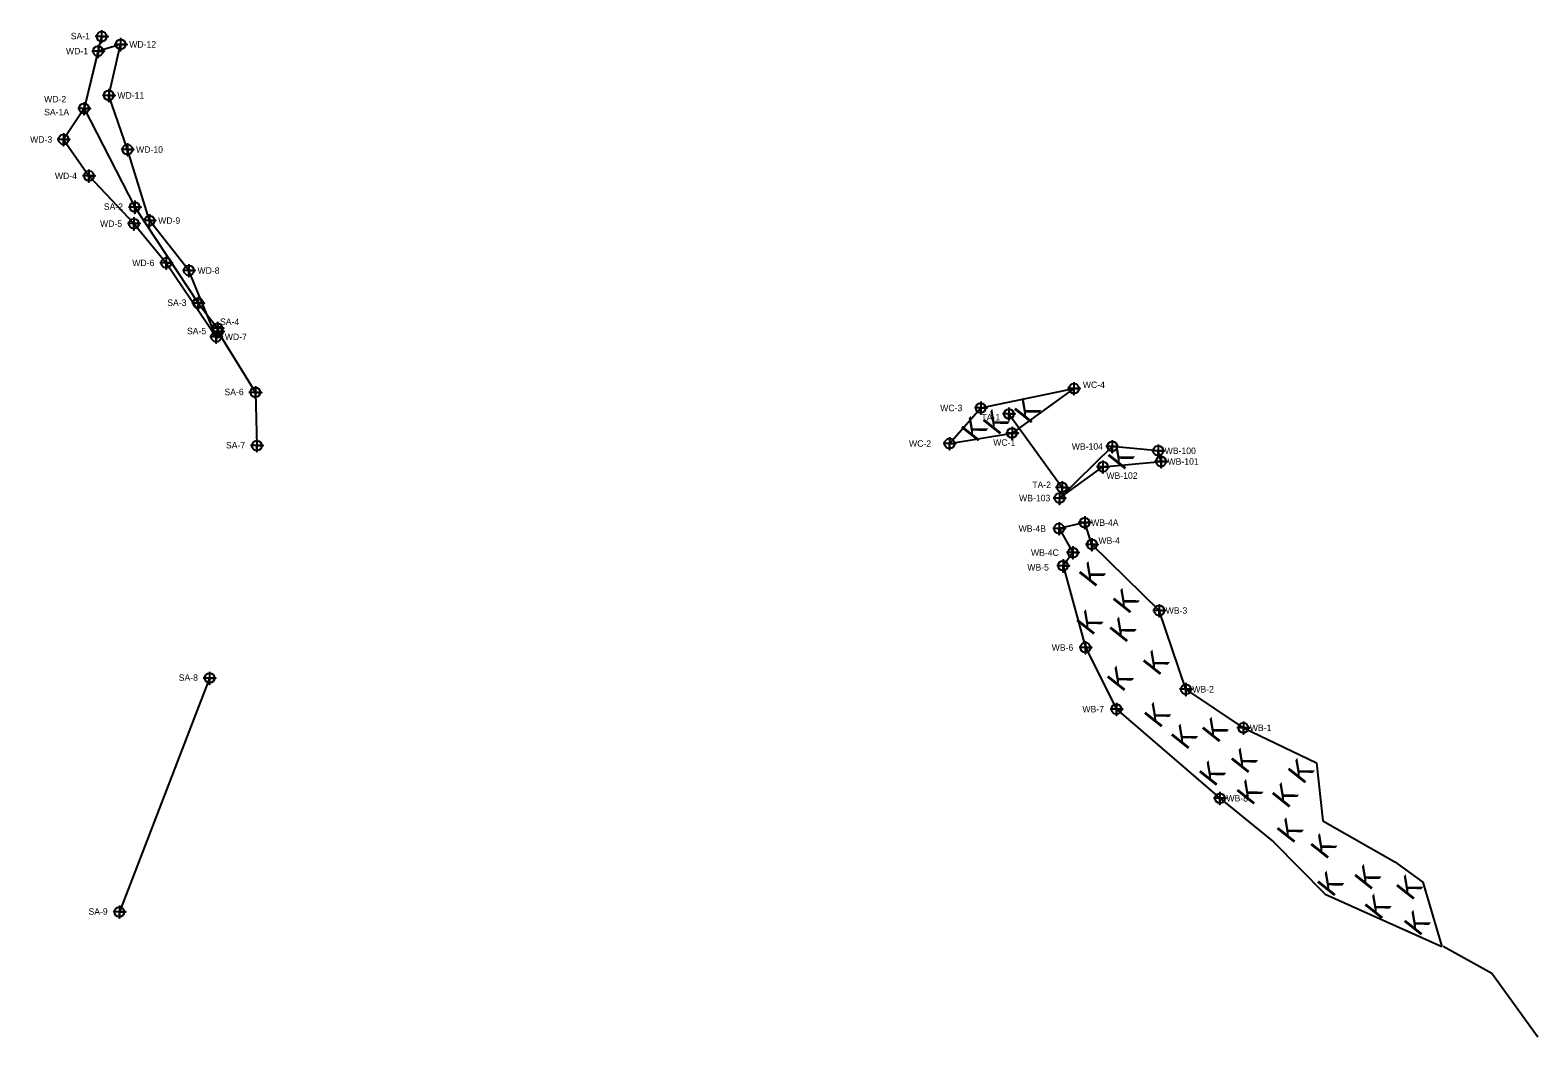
# Model space of a CAD drawing. Extents: x 1487542 to 1488992, y 498221 to 499418.
# Drawn here: x 1487542 to 1488253, y 498234 to 498709 of the extents above; entities that cross this region are included whole.
import ezdxf

# ---------------------------------------------------------------- set-up
doc = ezdxf.new("R2010")
doc.units = 0
for name, color, linetype in [('Exist Environmental Wetland Boundary', 7, 'Continuous'), ('Exist Environmental Wetland Boundary Cogo Point CELL', 7, 'Continuous'), ('Exist Environmental Wetland Boundary Text', 7, 'Continuous'), ('Exist Hydro Jurisdictional Stream or Body of Water Mitigable', 7, 'Continuous'), ('Exist Hydro Jurisdictional Stream or Body of Water Mitigable Cogo Point CELL', 7, 'Continuous'), ('Exist Hydro Jurisdictional Stream or Body of Water Mitigable Text', 7, 'Continuous'), ('WEX', 7, 'Continuous')]:
    doc.layers.add(name, color=color, linetype=linetype)

msp = doc.modelspace()

# ---------------------------------------------------------------- linework, layer by layer
at = {"layer": 'Exist Environmental Wetland Boundary'}
for p, q in [((1487989.85, 498530.79), (1488033.83, 498539.94)), ((1488033.83, 498539.94), (1488004.63, 498518.96)), ((1487975.14, 498514.02), (1487989.85, 498530.79)), ((1487975.14, 498514.02), (1488004.63, 498518.96)), ((1488027.05, 498488.31), (1488051.91, 498512.67)), ((1488073.57, 498510.61), (1488051.91, 498512.67)), ((1488047.52, 498503.04), (1488074.9, 498505.57)), ((1488074.9, 498505.57), (1488073.57, 498510.61)), ((1488027.05, 498488.31), (1488047.52, 498503.04)), ((1488027.05, 498488.31), (1488027.05, 498488.31)), ((1488038.89, 498476.72), (1488026.84, 498473.92)), ((1488042.31, 498466.47), (1488038.89, 498476.72)), ((1488026.84, 498473.92), (1488033.35, 498462.59)), ((1488033.35, 498462.59), (1488028.68, 498456.43)), ((1488042.31, 498466.47), (1488074.05, 498435.29)), ((1488028.68, 498456.43), (1488039.22, 498417.82)), ((1488086.63, 498398.13), (1488074.05, 498435.29)), ((1488039.22, 498417.82), (1488053.85, 498388.8)), ((1488113.73, 498379.96), (1488086.63, 498398.13)), ((1488053.85, 498388.8), (1488102.69, 498346.76)), ((1488113.73, 498379.96), (1488148.21, 498363.39)), ((1488148.21, 498363.39), (1488151.15, 498336.13)), ((1488102.69, 498346.76), (1488127.91, 498326.29)), ((1488151.15, 498336.13), (1488185.16, 498316.76)), ((1488127.91, 498326.29), (1488152.35, 498301.47)), ((1488185.16, 498316.76), (1488198.43, 498307.27)), ((1488198.43, 498307.27), (1488207.36, 498276.87)), ((1488152.35, 498301.47), (1488207.36, 498276.87))]:
    msp.add_line(p, q, dxfattribs=at)
msp.add_lwpolyline([(1487629.27, 498564.35), (1487616.38, 498595.61), (1487597.86, 498619.14), (1487587.44, 498652.62), (1487578.6, 498678.18), (1487584.22, 498702.23), (1487573.56, 498699.03), (1487566.96, 498672), (1487557.29, 498657.39), (1487569.27, 498640.21), (1487590.45, 498617.69), (1487605.69, 498599.19)], close=True, dxfattribs=at)
at = {"layer": 'Exist Environmental Wetland Boundary Cogo Point CELL'}
for points in [[(1487584.22, 498705.23), (1487584.22, 498699.23), (1487584.22, 498702.23), (1487587.22, 498702.23), (1487581.22, 498702.23)], [(1487573.56, 498702.03), (1487573.56, 498696.03), (1487573.56, 498699.03), (1487576.56, 498699.03), (1487570.56, 498699.03)], [(1487566.96, 498675), (1487566.96, 498669), (1487566.96, 498672), (1487569.96, 498672), (1487563.96, 498672)], [(1487578.6, 498681.18), (1487578.6, 498675.18), (1487578.6, 498678.18), (1487581.6, 498678.18), (1487575.6, 498678.18)], [(1487557.29, 498660.39), (1487557.29, 498654.39), (1487557.29, 498657.39), (1487560.29, 498657.39), (1487554.29, 498657.39)], [(1487587.44, 498655.62), (1487587.44, 498649.62), (1487587.44, 498652.62), (1487590.44, 498652.62), (1487584.44, 498652.62)], [(1487569.27, 498643.21), (1487569.27, 498637.21), (1487569.27, 498640.21), (1487572.27, 498640.21), (1487566.27, 498640.21)], [(1487590.45, 498620.69), (1487590.45, 498614.69), (1487590.45, 498617.69), (1487593.45, 498617.69), (1487587.45, 498617.69)], [(1487597.86, 498622.14), (1487597.86, 498616.14), (1487597.86, 498619.14), (1487600.86, 498619.14), (1487594.86, 498619.14)], [(1487605.69, 498602.19), (1487605.69, 498596.19), (1487605.69, 498599.19), (1487608.69, 498599.19), (1487602.69, 498599.19)], [(1487616.38, 498598.61), (1487616.38, 498592.61), (1487616.38, 498595.61), (1487619.38, 498595.61), (1487613.38, 498595.61)], [(1487629.27, 498567.35), (1487629.27, 498561.35), (1487629.27, 498564.35), (1487632.27, 498564.35), (1487626.27, 498564.35)], [(1488033.83, 498542.94), (1488033.83, 498536.94), (1488033.83, 498539.94), (1488036.83, 498539.94), (1488030.83, 498539.94)], [(1487989.85, 498533.79), (1487989.85, 498527.79), (1487989.85, 498530.79), (1487992.85, 498530.79), (1487986.85, 498530.79)], [(1488004.63, 498521.96), (1488004.63, 498515.96), (1488004.63, 498518.96), (1488007.63, 498518.96), (1488001.63, 498518.96)], [(1487975.14, 498517.02), (1487975.14, 498511.02), (1487975.14, 498514.02), (1487978.14, 498514.02), (1487972.14, 498514.02)], [(1488051.91, 498515.67), (1488051.91, 498509.67), (1488051.91, 498512.67), (1488054.91, 498512.67), (1488048.91, 498512.67)], [(1488073.57, 498513.61), (1488073.57, 498507.61), (1488073.57, 498510.61), (1488076.57, 498510.61), (1488070.57, 498510.61)], [(1488047.52, 498506.04), (1488047.52, 498500.04), (1488047.52, 498503.04), (1488050.52, 498503.04), (1488044.52, 498503.04)], [(1488074.9, 498508.57), (1488074.9, 498502.57), (1488074.9, 498505.57), (1488077.9, 498505.57), (1488071.9, 498505.57)], [(1488027.05, 498491.31), (1488027.05, 498485.31), (1488027.05, 498488.31), (1488030.05, 498488.31), (1488024.05, 498488.31)], [(1488026.84, 498476.92), (1488026.84, 498470.92), (1488026.84, 498473.92), (1488029.84, 498473.92), (1488023.84, 498473.92)], [(1488038.89, 498479.72), (1488038.89, 498473.72), (1488038.89, 498476.72), (1488041.89, 498476.72), (1488035.89, 498476.72)], [(1488042.31, 498469.47), (1488042.31, 498463.47), (1488042.31, 498466.47), (1488045.31, 498466.47), (1488039.31, 498466.47)], [(1488033.35, 498465.59), (1488033.35, 498459.59), (1488033.35, 498462.59), (1488036.35, 498462.59), (1488030.35, 498462.59)], [(1488028.68, 498459.43), (1488028.68, 498453.43), (1488028.68, 498456.43), (1488031.68, 498456.43), (1488025.68, 498456.43)], [(1488074.05, 498438.29), (1488074.05, 498432.29), (1488074.05, 498435.29), (1488077.05, 498435.29), (1488071.05, 498435.29)], [(1488039.22, 498420.82), (1488039.22, 498414.82), (1488039.22, 498417.82), (1488042.22, 498417.82), (1488036.22, 498417.82)], [(1488086.63, 498401.13), (1488086.63, 498395.13), (1488086.63, 498398.13), (1488089.63, 498398.13), (1488083.63, 498398.13)], [(1488053.85, 498391.8), (1488053.85, 498385.8), (1488053.85, 498388.8), (1488056.85, 498388.8), (1488050.85, 498388.8)], [(1488113.73, 498382.96), (1488113.73, 498376.96), (1488113.73, 498379.96), (1488116.73, 498379.96), (1488110.73, 498379.96)], [(1488102.69, 498349.76), (1488102.69, 498343.76), (1488102.69, 498346.76), (1488105.69, 498346.76), (1488099.69, 498346.76)]]:
    msp.add_lwpolyline(points, dxfattribs=at)
for centre in [(1487584.22, 498702.23), (1487573.56, 498699.03), (1487566.96, 498672), (1487578.6, 498678.18), (1487557.29, 498657.39), (1487587.44, 498652.62), (1487569.27, 498640.21), (1487590.45, 498617.69), (1487597.86, 498619.14), (1487605.69, 498599.19), (1487616.38, 498595.61), (1487629.27, 498564.35), (1488033.83, 498539.94), (1487989.85, 498530.79), (1488004.63, 498518.96), (1487975.14, 498514.02), (1488051.91, 498512.67), (1488073.57, 498510.61), (1488047.52, 498503.04), (1488074.9, 498505.57), (1488027.05, 498488.31), (1488026.84, 498473.92), (1488038.89, 498476.72), (1488042.31, 498466.47), (1488033.35, 498462.59), (1488028.68, 498456.43), (1488074.05, 498435.29), (1488039.22, 498417.82), (1488086.63, 498398.13), (1488053.85, 498388.8), (1488113.73, 498379.96), (1488102.69, 498346.76)]:
    msp.add_circle(centre, 2.34, dxfattribs=at)
at = {"layer": 'Exist Hydro Jurisdictional Stream or Body of Water Mitigable'}
for p, q in [((1488003.17, 498527.97), (1488028.2, 498493.32)), ((1488207.92, 498277.02), (1488230.95, 498264.36)), ((1488230.95, 498264.36), (1488252.62, 498234.27))]:
    msp.add_line(p, q, dxfattribs=at)
for points in [[(1487575.25, 498705.92), (1487566.96, 498672), (1487590.84, 498625.54), (1487620.76, 498580.23), (1487629.85, 498568.35), (1487630.05, 498566.84), (1487647.74, 498538.13), (1487648.45, 498513.03)], [(1487626.17, 498403.45), (1487583.61, 498293.17)]]:
    msp.add_lwpolyline(points, dxfattribs=at)
at = {"layer": 'Exist Hydro Jurisdictional Stream or Body of Water Mitigable Cogo Point CELL'}
for points in [[(1487575.25, 498708.92), (1487575.25, 498702.92), (1487575.25, 498705.92), (1487578.25, 498705.92), (1487572.25, 498705.92)], [(1487590.84, 498628.54), (1487590.84, 498622.54), (1487590.84, 498625.54), (1487593.84, 498625.54), (1487587.84, 498625.54)], [(1487620.76, 498583.23), (1487620.76, 498577.23), (1487620.76, 498580.23), (1487623.76, 498580.23), (1487617.76, 498580.23)], [(1487629.85, 498571.35), (1487629.85, 498565.35), (1487629.85, 498568.35), (1487632.85, 498568.35), (1487626.85, 498568.35)], [(1487630.05, 498569.84), (1487630.05, 498563.84), (1487630.05, 498566.84), (1487633.05, 498566.84), (1487627.05, 498566.84)], [(1487647.74, 498541.13), (1487647.74, 498535.13), (1487647.74, 498538.13), (1487650.74, 498538.13), (1487644.74, 498538.13)], [(1488003.17, 498530.97), (1488003.17, 498524.97), (1488003.17, 498527.97), (1488006.17, 498527.97), (1488000.17, 498527.97)], [(1487648.45, 498516.03), (1487648.45, 498510.03), (1487648.45, 498513.03), (1487651.45, 498513.03), (1487645.45, 498513.03)], [(1488028.2, 498496.32), (1488028.2, 498490.32), (1488028.2, 498493.32), (1488031.2, 498493.32), (1488025.2, 498493.32)], [(1487626.17, 498406.45), (1487626.17, 498400.45), (1487626.17, 498403.45), (1487629.17, 498403.45), (1487623.17, 498403.45)], [(1487583.61, 498296.17), (1487583.61, 498290.17), (1487583.61, 498293.17), (1487586.61, 498293.17), (1487580.61, 498293.17)]]:
    msp.add_lwpolyline(points, dxfattribs=at)
for centre in [(1487575.25, 498705.92), (1487590.84, 498625.54), (1487620.76, 498580.23), (1487629.85, 498568.35), (1487630.05, 498566.84), (1487647.74, 498538.13), (1488003.17, 498527.97), (1487648.45, 498513.03), (1488028.2, 498493.32), (1487626.17, 498403.45), (1487583.61, 498293.17)]:
    msp.add_circle(centre, 2.34, dxfattribs=at)
at = {"layer": 'WEX'}
for p, q in [((1487573.56, 498699.03), (1487573.56, 498699.03)), ((1487584.22, 498702.23), (1487584.22, 498702.23)), ((1487578.6, 498678.18), (1487578.6, 498678.18)), ((1487566.96, 498672), (1487566.96, 498672)), ((1487557.29, 498657.39), (1487557.29, 498657.39)), ((1487587.44, 498652.62), (1487587.44, 498652.62)), ((1487569.27, 498640.21), (1487569.27, 498640.21)), ((1487590.84, 498625.54), (1487590.84, 498625.54)), ((1487590.45, 498617.69), (1487590.45, 498617.69)), ((1487597.86, 498619.14), (1487597.86, 498619.14)), ((1487605.69, 498599.19), (1487605.69, 498599.19)), ((1487616.38, 498595.61), (1487616.38, 498595.61)), ((1487620.76, 498580.23), (1487620.76, 498580.23)), ((1487620.76, 498580.23), (1487620.76, 498580.23)), ((1487629.83, 498568.12), (1487629.83, 498568.12)), ((1487629.83, 498568.12), (1487629.83, 498568.12)), ((1487629.27, 498564.35), (1487629.27, 498564.35)), ((1487630.05, 498566.84), (1487630.05, 498566.84)), ((1487630.05, 498566.84), (1487630.05, 498566.84)), ((1487647.74, 498538.13), (1487647.74, 498538.13)), ((1487648.45, 498513.03), (1487648.45, 498513.03)), ((1487626.17, 498403.45), (1487626.17, 498403.45)), ((1487583.61, 498293.17), (1487583.61, 498293.17))]:
    msp.add_line(p, q, dxfattribs=at)

# ---------------------------------------------------------------- texts
at = {"layer": 'Exist Environmental Wetland Boundary'}
for p in [(1488012.87, 498522.75), (1487987.87, 498514.16), (1487998.08, 498517.46), (1488057.04, 498500.92), (1488043.4, 498445.74), (1488059.41, 498433.15), (1488042.25, 498423.04), (1488057.87, 498419.53), (1488073.59, 498404.03), (1488056.65, 498396.47), (1488074.19, 498379.36), (1488101.49, 498372.33), (1488086.88, 498369.13), (1488115.16, 498357.8), (1488100.09, 498351.8), (1488141.94, 498352.95), (1488117.77, 498342.93), (1488134.49, 498341.52), (1488136.74, 498324.96), (1488152.62, 498317.47), (1488155.79, 498299.77), (1488173.3, 498302.9), (1488193.07, 498298.09), (1488178.16, 498288.97), (1488196.71, 498281.27)]:
    msp.add_text('K', height=10.2, rotation=51.5264, dxfattribs=at).set_placement(p)
at = {"layer": 'Exist Environmental Wetland Boundary Text'}
for s, p in [('WD-12', (1487588.28, 498700.71)), ('WD-1', (1487558.43, 498697.51)), ('WD-2', (1487548.13, 498674.85)), ('WD-11', (1487582.66, 498676.65)), ('SA-1A', (1487548.13, 498668.76)), ('WD-3', (1487541.52, 498655.86)), ('WD-10', (1487591.49, 498651.1)), ('WD-4', (1487553.2, 498638.68)), ('WD-5', (1487574.51, 498616.16)), ('WD-9', (1487601.91, 498617.62)), ('WD-6', (1487589.7, 498597.66)), ('WD-8', (1487620.44, 498594.09)), ('WD-7', (1487633.33, 498562.83)), ('WC-4', (1488038.03, 498540.19)), ('WC-3', (1487970.75, 498529.26)), ('WC-2', (1487956.04, 498512.5)), ('WC-1', (1487995.77, 498512.96)), ('WB-104', (1488032.81, 498511.14)), ('WB-100', (1488076.62, 498509.08)), ('WB-101', (1488077.95, 498504.05)), ('WB-102', (1488049.13, 498497.37)), ('WB-103', (1488007.96, 498486.79)), ('WB-4B', (1488007.74, 498472.4)), ('WB-4A', (1488041.94, 498475.2)), ('WB-4', (1488045.36, 498466.77)), ('WB-4C', (1488013.56, 498461.07)), ('WB-5', (1488011.84, 498454.13)), ('WB-3', (1488077.09, 498433.77)), ('WB-6', (1488023.32, 498416.3)), ('WB-2', (1488089.67, 498396.61)), ('WB-7', (1488037.82, 498387.27)), ('WB-1', (1488116.77, 498378.44)), ('WB-8', (1488105.74, 498345.24))]:
    msp.add_text(s, height=3.047, dxfattribs=at).set_placement(p)
at = {"layer": 'Exist Hydro Jurisdictional Stream or Body of Water Mitigable Text'}
for s, p in [('SA-1', (1487560.69, 498704.6)), ('SA-2', (1487576.28, 498624.22)), ('SA-3', (1487606.2, 498578.9)), ('SA-5', (1487615.49, 498565.52)), ('SA-4', (1487631.08, 498569.92)), ('SA-6', (1487633.18, 498536.81)), ('TA-1', (1487990.2, 498524.92)), ('SA-7', (1487633.88, 498511.71)), ('TA-2', (1488014.18, 498493.04)), ('SA-8', (1487611.61, 498402.13)), ('SA-9', (1487569.05, 498291.85))]:
    msp.add_text(s, height=3.047, dxfattribs=at).set_placement(p)

doc.saveas('drawing.dxf')
